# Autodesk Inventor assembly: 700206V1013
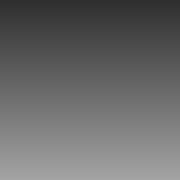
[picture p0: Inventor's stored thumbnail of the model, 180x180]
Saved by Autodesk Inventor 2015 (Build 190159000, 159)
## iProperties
Created: 2020-02
Part Number: 700206V1013
Document SubType Name: Assembly
Designer: 1026954
Author: 1026954
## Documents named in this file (1)
- C:\Users\1026954\Desktop\700206V1013\700206V1013.iam
